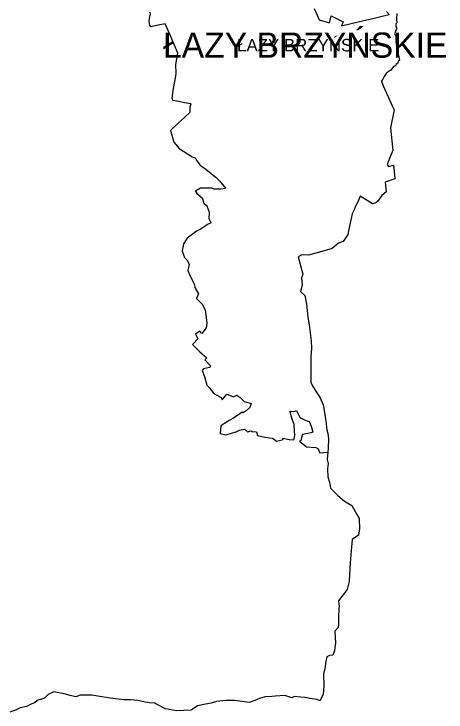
# Model space of a CAD drawing. Extents: x -562952 to -547638, y 190691 to 208158.
# Drawn here: x -551969 to -548882, y 191461 to 196451 of the extents above; entities that cross this region are included whole.
import ezdxf

# ---------------------------------------------------------------- set-up
doc = ezdxf.new("R2010")
doc.units = 0
for name, color, linetype in [('granica_gminy', 7, 'Continuous'), ('granica_sołectwa', 7, 'Continuous'), ('nazwy miejscowości', 7, 'Continuous'), ('nazwy miejscowości DUŻE', 7, 'Continuous'), ('obwódka', 7, 'Continuous')]:
    doc.layers.add(name, color=color, linetype=linetype)

msp = doc.modelspace()

# ---------------------------------------------------------------- linework, layer by layer
at = {"layer": 'granica_gminy'}
for points in [[(-549824.8, 196489.7), (-549803.3, 196443.6), (-549787.6, 196409.2), (-549715.4, 196388.4), (-549702.4, 196438.1), (-549655, 196414.4), (-549617.6, 196395.8), (-549629.6, 196367.4), (-549620.1, 196368.8), (-549509.9, 196395.9), (-549395.1, 196421.6), (-549328.8, 196437.1), (-549289.2, 196447.6), (-549307.2, 196467.8)], [(-549233.9, 196454.2), (-549234.4, 196447.7), (-549237, 196423.2), (-549236.4, 196413.5), (-549233.9, 196387), (-549240.1, 196381.5), (-549241.7, 196367.2), (-549239, 196359.2), (-549236.5, 196352.1), (-549233.9, 196346.4), (-549239.3, 196338.2), (-549241.9, 196331.1), (-549246.4, 196318.9), (-549249.6, 196309.8), (-549241.1, 196291.3), (-549241.6, 196258), (-549237.9, 196233.2), (-549235.8, 196218.5), (-549232.8, 196210.4), (-549224.2, 196190.4), (-549236.9, 196170.3), (-549226.8, 196162.5), (-549222.4, 196156), (-549215.4, 196119.1), (-549221.2, 196113.4), (-549227.5, 196103.8), (-549229, 196097.2), (-549239.7, 196090.6), (-549243.7, 196080.7), (-549257.6, 196074.9), (-549276.9, 196050.2), (-549286.7, 196045.2), (-549310.3, 196025.6), (-549324.4, 196003.9), (-549333.7, 195984.7), (-549344.9, 195971.3), (-549342.9, 195966.4), (-549339.5, 195958.5), (-549330.4, 195938.1), (-549318.5, 195910.4), (-549306.6, 195883.9), (-549293.7, 195854.3), (-549268.8, 195799.6), (-549262.4, 195784.4), (-549253.5, 195764.7), (-549279.7, 195636.6), (-549262.9, 195474.6), (-549285.6, 195419.1), (-549301.9, 195375.5), (-549293.9, 195360.8), (-549258.2, 195371.2), (-549248.7, 195277.9), (-549248.5, 195272.7), (-549317.5, 195249.8), (-549309.9, 195180.5), (-549341.9, 195154), (-549372.5, 195110.1), (-549384.7, 195101.9), (-549406.4, 195093.6), (-549496.6, 195148.9), (-549505.4, 195124.5), (-549530.4, 195069.4), (-549538.8, 195050.6), (-549551.6, 195022.8), (-549567.8, 194955.4), (-549579, 194901.3), (-549582.6, 194874.3), (-549617.4, 194824.3), (-549651.5, 194813.1), (-549694.7, 194775.4), (-549786.7, 194747.7), (-549864.9, 194727.8), (-549912.6, 194728.2), (-549938.4, 194714.4), (-549929.5, 194679), (-549905.9, 194590.3), (-549915.1, 194564.4), (-549910.7, 194513.3), (-549921, 194468.4), (-549890.5, 194439.7), (-549879, 194376.2), (-549868.9, 194283.7), (-549859.9, 194229.4), (-549845, 194113.7), (-549842.6, 194063.2), (-549844, 194057.6), (-549847.1, 194003.2), (-549847.4, 193965.1), (-549847.9, 193957.4), (-549849.2, 193912.5), (-549848.7, 193855.8), (-549847.5, 193819.6), (-549836.9, 193791.7), (-549804.4, 193742.9), (-549783.4, 193711.4), (-549759.4, 193658), (-549751.2, 193603.1), (-549738.6, 193524.6), (-549737.1, 193495.9), (-549732.6, 193478), (-549727.2, 193452.3), (-549722.7, 193416.9), (-549723, 193347.1), (-549726.7, 193317.7), (-549731.2, 193265.5), (-549724.2, 193237.4), (-549728.6, 193199.4), (-549727.2, 193143.4), (-549714.6, 193104.2), (-549706.5, 193061.4), (-549656.2, 193008.2), (-549608.3, 192967.3), (-549555.5, 192937.3), (-549519, 192872.1), (-549502.7, 192845.5), (-549500.5, 192771.6), (-549506.4, 192726.2), (-549553, 192695.2), (-549557.1, 192642.5), (-549565.9, 192528.8), (-549571.8, 192444.5), (-549574.8, 192393.7), (-549587.7, 192336.8), (-549650.9, 192256.9), (-549645.7, 192217), (-549646.8, 192201.3), (-549651.3, 192139.6), (-549651.3, 192087.1), (-549653.1, 192066.4), (-549677.5, 192039.1), (-549672, 191953.2), (-549675.7, 191922.1), (-549679.7, 191898.1), (-549690.1, 191867.8), (-549714.1, 191865.6), (-549733.3, 191854.5), (-549741.1, 191822.5), (-549748.1, 191769.5), (-549756.6, 191733.2), (-549755.1, 191648.2), (-549759.9, 191585.8), (-549783, 191541.7), (-549802.7, 191549.7), (-549854.2, 191557.1), (-549891.9, 191563.9), (-549919.6, 191567.4), (-549965.8, 191572.5), (-549984, 191563.4), (-550033, 191578.7), (-550103.5, 191574.1), (-550125.6, 191572.5), (-550173.8, 191568.7), (-550214.1, 191556.8), (-550249.3, 191544), (-550289.7, 191529), (-550354.5, 191538.8), (-550393.1, 191542.8), (-550454.6, 191543), (-550522.6, 191535.7), (-550560.6, 191524.8), (-550599.7, 191516.5), (-550657.3, 191504.3), (-550702.4, 191474.5), (-550808.5, 191469.6), (-550887.2, 191482.9), (-550949.8, 191517.1), (-550963.9, 191523.6), (-551003, 191526.2), (-551031.9, 191532), (-551083.7, 191542.6), (-551137.7, 191548.7), (-551185.2, 191547.6), (-551262.8, 191556.7), (-551281.9, 191559.8), (-551369.4, 191575.4), (-551413.4, 191582.6), (-551496.4, 191582.2), (-551528.4, 191570), (-551568.2, 191580.3), (-551609.7, 191590.6), (-551685.4, 191605.9), (-551726.1, 191586.2), (-551752.1, 191559), (-551803.5, 191542.6), (-551822.9, 191527), (-551842.7, 191518.6), (-551880.3, 191500.7), (-551924.5, 191490.1), (-551954.3, 191476.3), (-551997.7, 191461)]]:
    msp.add_lwpolyline(points, dxfattribs=at)
at = {"layer": 'granica_sołectwa'}
for points in [[(-550798.2, 195668), (-550747.4, 195714.2), (-550713.8, 195746.1), (-550709.1, 195750.8), (-550710.2, 195786.8), (-550702.7, 195808.3), (-550749.9, 195816.8), (-550791.1, 195825), (-550833.7, 195831.6), (-550839.5, 195849.2), (-550833.2, 195884.2), (-550828.4, 195917.7), (-550812.9, 196006.5), (-550809.5, 196027), (-550812.4, 196089.1), (-550799.5, 196171.5), (-550825.4, 196232.8), (-550851.6, 196294.5), (-550888.4, 196380.2), (-550939.6, 196370), (-550991.8, 196359.5), (-550997.9, 196370.5), (-551003.2, 196397), (-551001.1, 196420.1), (-550995, 196441), (-550993.7, 196448.1), (-550995.7, 196463.2)], [(-550798.2, 195668), (-550850.9, 195618.5), (-550826.5, 195535.7), (-550789.9, 195488.9), (-550696.4, 195428.7), (-550674.3, 195422.1), (-550662, 195401.2), (-550639.5, 195371), (-550598.4, 195342.1), (-550548.6, 195301.1), (-550527.5, 195284.8), (-550499.8, 195258.8), (-550458.7, 195205.1)], [(-550560, 194959), (-550574.2, 194985.7), (-550571.4, 195031.4), (-550589, 195077.2), (-550610, 195094.8), (-550619.3, 195129.9), (-550656.3, 195160.8), (-550671.4, 195185.8), (-550636.2, 195209.2), (-550556.3, 195208.7), (-550541.8, 195200.6), (-550493.7, 195201.2), (-550458.7, 195205.1)], [(-550560, 194959), (-550580.7, 194947.7), (-550631.3, 194914.4), (-550665, 194898.2), (-550686.2, 194883), (-550732.4, 194847.3), (-550756.8, 194807.4)], [(-550756.8, 194807.4), (-550768.2, 194756.1), (-550751.4, 194709.5), (-550733.5, 194693.2), (-550718.2, 194661.6), (-550727, 194617.5), (-550715.5, 194588.1), (-550679.3, 194515.1), (-550676.5, 194496)], [(-550676.5, 194496), (-550650.4, 194451.6), (-550665.7, 194416.3), (-550625.5, 194377.7), (-550602.8, 194336.5), (-550596.7, 194282.4), (-550591.3, 194240.1), (-550596.7, 194206.6), (-550627.4, 194166.2), (-550642.3, 194183.5), (-550672.8, 194161.9), (-550658.2, 194136.4), (-550653.5, 194130.4), (-550694.1, 194088.8), (-550642, 194036.5), (-550591.7, 193992.5), (-550605, 193978.4), (-550562.5, 193933.8)], [(-550562.5, 193933.8), (-550572.8, 193924.3), (-550615.8, 193914.1), (-550625.7, 193903.3), (-550609, 193858.6), (-550590.4, 193798.8), (-550573.4, 193780.1), (-550541.6, 193737.6), (-550489.6, 193708.3), (-550482.6, 193693.4), (-550447.1, 193733.3), (-550417.6, 193721.6), (-550402.7, 193714), (-550377.6, 193727.1)], [(-550377.6, 193727.1), (-550352.1, 193708.3), (-550325, 193681.5), (-550275.2, 193666.1), (-550283.1, 193638.9)], [(-550283.1, 193638.9), (-550309.3, 193613.8), (-550331.5, 193599.7), (-550339.2, 193604.2), (-550372.9, 193580.1), (-550406.1, 193560.2), (-550431.2, 193544.6), (-550446.8, 193535.4), (-550491.5, 193507.7), (-550495.1, 193451.9), (-550456.4, 193443), (-550381.7, 193463.7), (-550356.6, 193475.5), (-550323, 193483.7), (-550300.8, 193463), (-550275, 193471.8), (-550266.1, 193465.5), (-550235.8, 193465.2), (-550230.2, 193438.4), (-550177.8, 193425.4), (-550123.1, 193419.4), (-550093.1, 193398.4), (-550046.7, 193409.5), (-550047.1, 193419.4), (-550004, 193409.8), (-549969.6, 193406.8), (-549962, 193437.2), (-549964.8, 193471.2), (-549968.1, 193517.3), (-549982.6, 193555.3), (-549990.8, 193587.8), (-549995.3, 193610.7), (-549969, 193610.5), (-549951.3, 193615.8)], [(-549951.3, 193615.8), (-549945.5, 193604.2), (-549927.8, 193568.7), (-549916.3, 193561.8), (-549889.2, 193547), (-549859.1, 193537.7)], [(-549859.1, 193537.7), (-549844.8, 193503.5), (-549832.8, 193461), (-549847.8, 193455.8), (-549868.4, 193452), (-549910.6, 193444.8), (-549920.6, 193400.9), (-549928.9, 193397.7), (-549878.9, 193356.1), (-549812, 193352), (-549795.4, 193343.5), (-549782.6, 193314.5), (-549726.7, 193317.7)]]:
    msp.add_lwpolyline(points, dxfattribs=at)
at = {"layer": 'obwódka'}
for points in [[(-549824.8, 196489.7), (-549803.3, 196443.6), (-549787.6, 196409.2), (-549715.4, 196388.4), (-549702.4, 196438.1), (-549655, 196414.4), (-549617.6, 196395.8), (-549629.6, 196367.4), (-549620.1, 196368.8), (-549509.9, 196395.9), (-549395.1, 196421.6), (-549328.8, 196437.1), (-549289.2, 196447.6), (-549307.2, 196467.8)], [(-549233.9, 196454.2), (-549234.4, 196447.7), (-549237, 196423.2), (-549236.4, 196413.5), (-549233.9, 196387), (-549240.1, 196381.5), (-549241.7, 196367.2), (-549239, 196359.2), (-549236.5, 196352.1), (-549233.9, 196346.4), (-549239.3, 196338.2), (-549241.9, 196331.1), (-549246.4, 196318.9), (-549249.6, 196309.8), (-549241.1, 196291.3), (-549241.6, 196258), (-549237.9, 196233.2), (-549235.8, 196218.5), (-549232.8, 196210.4), (-549224.2, 196190.4), (-549236.9, 196170.3), (-549226.8, 196162.5), (-549222.4, 196156), (-549215.4, 196119.1), (-549221.2, 196113.4), (-549227.5, 196103.8), (-549229, 196097.2), (-549239.7, 196090.6), (-549243.7, 196080.7), (-549257.6, 196074.9), (-549276.9, 196050.2), (-549286.7, 196045.2), (-549310.3, 196025.6), (-549324.4, 196003.9), (-549333.7, 195984.7), (-549344.9, 195971.3), (-549342.9, 195966.4), (-549339.5, 195958.5), (-549330.4, 195938.1), (-549318.5, 195910.4), (-549306.6, 195883.9), (-549293.7, 195854.3), (-549268.8, 195799.6), (-549262.4, 195784.4), (-549253.5, 195764.7), (-549279.7, 195636.6), (-549262.9, 195474.6), (-549285.6, 195419.1), (-549301.9, 195375.5), (-549293.9, 195360.8), (-549258.2, 195371.2), (-549248.7, 195277.9), (-549248.5, 195272.7), (-549317.5, 195249.8), (-549309.9, 195180.5), (-549341.9, 195154), (-549372.5, 195110.1), (-549384.7, 195101.9), (-549406.4, 195093.6), (-549496.6, 195148.9), (-549505.4, 195124.5), (-549530.4, 195069.4), (-549538.8, 195050.6), (-549551.6, 195022.8), (-549567.8, 194955.4), (-549579, 194901.3), (-549582.6, 194874.3), (-549617.4, 194824.3), (-549651.5, 194813.1), (-549694.7, 194775.4), (-549786.7, 194747.7), (-549864.9, 194727.8), (-549912.6, 194728.2), (-549938.4, 194714.4), (-549929.5, 194679), (-549905.9, 194590.3), (-549915.1, 194564.4), (-549910.7, 194513.3), (-549921, 194468.4), (-549890.5, 194439.7), (-549879, 194376.2), (-549868.9, 194283.7), (-549859.9, 194229.4), (-549845, 194113.7), (-549842.6, 194063.2), (-549844, 194057.6), (-549847.1, 194003.2), (-549847.4, 193965.1), (-549847.9, 193957.4), (-549849.2, 193912.5), (-549848.7, 193855.8), (-549847.5, 193819.6), (-549836.9, 193791.7), (-549804.4, 193742.9), (-549783.4, 193711.4), (-549759.4, 193658), (-549751.2, 193603.1), (-549738.6, 193524.6), (-549737.1, 193495.9), (-549732.6, 193478), (-549727.2, 193452.3), (-549722.7, 193416.9), (-549723, 193347.1), (-549726.7, 193317.7), (-549731.2, 193265.5), (-549724.2, 193237.4), (-549728.6, 193199.4), (-549727.2, 193143.4), (-549714.6, 193104.2), (-549706.5, 193061.4), (-549656.2, 193008.2), (-549608.3, 192967.3), (-549555.5, 192937.3), (-549519, 192872.1), (-549502.7, 192845.5), (-549500.5, 192771.6), (-549506.4, 192726.2), (-549553, 192695.2), (-549557.1, 192642.5), (-549565.9, 192528.8), (-549571.8, 192444.5), (-549574.8, 192393.7), (-549587.7, 192336.8), (-549650.9, 192256.9), (-549645.7, 192217), (-549646.8, 192201.3), (-549651.3, 192139.6), (-549651.3, 192087.1), (-549653.1, 192066.4), (-549677.5, 192039.1), (-549672, 191953.2), (-549675.7, 191922.1), (-549679.7, 191898.1), (-549690.1, 191867.8), (-549714.1, 191865.6), (-549733.3, 191854.5), (-549741.1, 191822.5), (-549748.1, 191769.5), (-549756.6, 191733.2), (-549755.1, 191648.2), (-549759.9, 191585.8), (-549783, 191541.7), (-549802.7, 191549.7), (-549854.2, 191557.1), (-549891.9, 191563.9), (-549919.6, 191567.4), (-549965.8, 191572.5), (-549984, 191563.4), (-550033, 191578.7), (-550103.5, 191574.1), (-550125.6, 191572.5), (-550173.8, 191568.7), (-550214.1, 191556.8), (-550249.3, 191544), (-550289.7, 191529), (-550354.5, 191538.8), (-550393.1, 191542.8), (-550454.6, 191543), (-550522.6, 191535.7), (-550560.6, 191524.8), (-550599.7, 191516.5), (-550657.3, 191504.3), (-550702.4, 191474.5), (-550808.5, 191469.6), (-550887.2, 191482.9), (-550949.8, 191517.1), (-550963.9, 191523.6), (-551003, 191526.2), (-551031.9, 191532), (-551083.7, 191542.6), (-551137.7, 191548.7), (-551185.2, 191547.6), (-551262.8, 191556.7), (-551281.9, 191559.8), (-551369.4, 191575.4), (-551413.4, 191582.6), (-551496.4, 191582.2), (-551528.4, 191570), (-551568.2, 191580.3), (-551609.7, 191590.6), (-551685.4, 191605.9), (-551726.1, 191586.2), (-551752.1, 191559), (-551803.5, 191542.6), (-551822.9, 191527), (-551842.7, 191518.6), (-551880.3, 191500.7), (-551924.5, 191490.1), (-551954.3, 191476.3), (-551997.7, 191461)]]:
    msp.add_lwpolyline(points, dxfattribs=at)

# ---------------------------------------------------------------- texts
at = {"layer": 'nazwy miejscowości'}
msp.add_text('ŁAZY BRZYŃSKIE', height=90, dxfattribs=at).set_placement((-550374.8, 196183.3))
at = {"layer": 'nazwy miejscowości DUŻE'}
msp.add_text('ŁAZY BRZYŃSKIE', height=180, dxfattribs=at).set_placement((-550904.8, 196138.3))

doc.saveas('drawing.dxf')
